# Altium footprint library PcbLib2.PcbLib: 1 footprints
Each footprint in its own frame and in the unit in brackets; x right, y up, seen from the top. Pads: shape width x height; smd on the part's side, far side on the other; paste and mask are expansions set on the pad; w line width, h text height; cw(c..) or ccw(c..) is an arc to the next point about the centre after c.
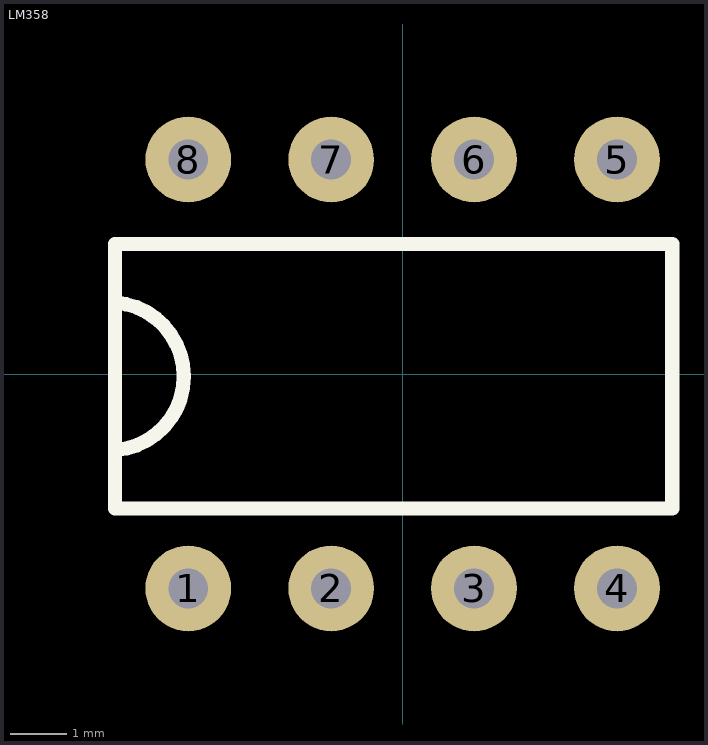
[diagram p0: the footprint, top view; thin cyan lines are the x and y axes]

## LM358 [mil]
pads (8):
  round 60 hole 27.95: 1(-150,-150) 2(-50,-150) 3(50,-150) 4(150,-150) 5(150,150) 6(50,150) 7(-50,150) 8(-150,150)
Top Overlay:
  lines w10: -201.18,50 cw(c-204.87,-1.65) -200.93,-53.28 ; -201.18,-94.09 188.58,-94.09 188.58,90.94 -201.18,90.94 -201.18,-94.09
